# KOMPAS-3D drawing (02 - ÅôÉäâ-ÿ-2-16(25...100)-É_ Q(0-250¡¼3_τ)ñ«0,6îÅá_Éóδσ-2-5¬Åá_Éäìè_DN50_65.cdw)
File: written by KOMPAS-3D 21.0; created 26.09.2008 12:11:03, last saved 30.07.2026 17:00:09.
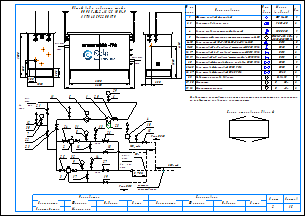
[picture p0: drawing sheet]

Sheets 1-2: A3, landscape

Document properties: Наименование: Макро:21; Автор: RaskoAdmin; Форматы листов документа: 2xA3; Полное имя файла: \\UR38nt01\Departments\КТО\КБ ПУРДГ\Заявки\Прайс-лист на типовые шкафы ГРПШ\ПУРДГ_стандарт_30_04_2026\ПУРДГ с РДНК\ПУРДГ-Ш-2-16(25...100)-Р_ Q(0-250нм3_ч)до0,6МПа_Рвых-2-5кПа_РДНК_DN50_65.cdw

Title block, sheet 1: Наименование: Пункт учета газа / ПУГ-Ш-400-Р / ЛГТИ.485922.001ТУ; designation: ЛГТИ.03.4411141; sheet number: 1; Количество листов документа: 2; organisation: ООО "ЭЛЬСТЕР Газэлектроника"; Форматы листов документа: A3; stored path: C:\Рабочие документы\Компас\ПУГ\Схема.cdw; Разработал: Устинов; Проверил: Кошкин; Утвердил: Кошкин
Title block, sheet 2: sheet number: 2; stored path: D:\Рабочие документы\Заявки\ПУРДГ\ПУРДГ-ШУЭО-2-100-Р 4411220.cdw; designation, second copy: ЛГТИ.03.4411141-

Views: Вид 1, Вид 2
Referenced files: wcvoit.frw
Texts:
  Normal
  № на
  схеме
  Усл.
  обозн.
  Марка
  (модель)
  Кол.
  Фильтр газовый фланцевый
  ФГ 16-50
  Регулятор давления газа
  РДНК-50
  Клапан предохранительный сбросной
  КПС DN20
  Измерительный комплекс с ротационным счетчиком Ду50
  СГ-ЭК-Р-(0,2...2,0)-
  Кран кнопочный VE-РАСКО-НЗ-1,6-G1/2-М20
  DN15
  Кран шаровой "под приварку" штуцерный DN20 PN16
  DN20
  Кран шаровой "под приварку" штуцерный DN15 PN16
  Кран шаровой "под приварку" штуцерный п/п DN15 PN16
  Кран шаровой фланцевый с мех. приводом DN50 PN16
  Кран шаровой фланцевый DN50 PN16
  Кран шаровой фланцевый DN65 PN16
  DN50
  DN65
  Индикатор перепада давления
  Манометр
  Манометр-напоромер
  Delta 15
  0...     МПа
  0...     кПа
  Общий вид и габариты шкафа
  ПУРДГ-Ш-2-16(25...100)-Р
  Выход газа
  Вход газа
  logo-rasko-ge.png
  DN 1
  местное
  сопротивление
  Римп DN15
  Римп DN20
  Выход
  газа
  Р=     кПа
  Вход
  Р=       МПа
  PDI
  Схема открывания дверей
  Предприятие изготовитель может заменять комплектующие на аналогичные,
  не ухудшающие заявленных характеристик.
  Должность
  Конструктор
  Фамилия
  Подпись
  Дата
  Согласовано
  Максимкин
  Лист
  Листов
  POLYLINE_STYLE_0.18_RGB_0_0_0
  POLYLINE_STYLE_0.50_RGB_0_0_0
  POLYLINE_STYLE_0.34_RGB_0_0_0
  PHANTOM_RGB_0_0_0_SC_1_THICK_0.18
  K5LT_THIN_RGB_0_0_0_THICK_0.18
  K5LT32769_RGB_0_0_0_THICK_0.18
  K5LT12_RGB_0_0_0_SC_1_THICK_0.18
  K5LT_DASHED_RGB_0_0_0_SC_1_THICK_0.18
  ACISOTGL_RGB_0_0_0_SC_0.8_THICK_0.25
  CONTINUOUS_RGB_0_127_31_THICK_0.3
  CONTINUOUS_RGB_0_0_255_THICK_0.35
  CONTINUOUS_RGB_255_0_0_THICK_0.35
  POLYLINE_STYLE_0.25_RGB_0_0_0
  CONTINUOUS_RGB_0_0_0_THICK_0.5
  POLYLINE_STYLE_0.35_RGB_0_0_255
  CONTINUOUS_RGB_0_0_0_THICK_0.4
  CONTINUOUS_RGB_0_0_0_THICK_0.35
  НЕВИДИМАЯ_RGB_0_0_0_SC_0.3_THICK_0.25
  СONTINUOUS_RGB_0_0_0_THICK_0.25
  ОСЕВАЯ2_RGB_248_153_30_SC_0.3_THICK_0.25
  Без оформления
Dimensions and other numbers on the sheet: 1; 2, 3; 2; 4; 5; 6-10; 11-15; 16, 17; 18, 19; 20; 21-25; 26, 27; 28; 29, 30; 31, 32; 1500; 250; 300; 1050; 550; 305; 2300; 4130; 2000; 2600; 5,,,7DN 1; 7; 30; 12; 21; 22; 23; 11; 6; 29; 24; 31; 8; 16; 13; 26; 18; 10; 15; 25; 32; 9; 3; 17; 14; 27; 19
